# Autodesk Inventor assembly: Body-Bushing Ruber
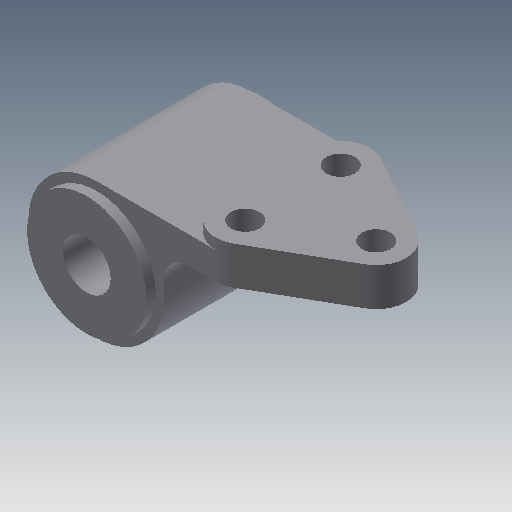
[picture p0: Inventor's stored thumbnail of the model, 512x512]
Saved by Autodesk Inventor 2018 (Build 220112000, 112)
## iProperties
Created: 2011-07
Part Number: Body-Bushing Ruber
Document SubType Name: Assembly
Designer: CadCim
Author: CadCim
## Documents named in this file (3)
- E:\_Deepak\Inventor\Autodesk Inventor_2017_Project\Resources\Inventor_2018_tut\c09_Inv_tut_2018\c09_tut03_inv\Anti Vibration Mount\Body-Bushing Ruber.iam
- E:\_Deepak\Inventor\Autodesk Inventor_2017_Project\Resources\Inventor_2018_tut\c09_Inv_tut_2018\c09_tut03_inv\Anti Vibration Mount\Body.ipt
- E:\_Deepak\Inventor\Autodesk Inventor_2017_Project\Resources\Inventor_2018_tut\c09_Inv_tut_2018\c09_tut03_inv\Anti Vibration Mount\Bushing Rubber.ipt
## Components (3 placed, 2 different names)
1. Body:1 — Insert:1, Insert:2
2. Bushing Rubber:1 — Insert:1
3. Bushing Rubber:2 — Insert:2
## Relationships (2: Insert 2)
- Insert:1: Body:1 ↔ Bushing Rubber:1
- Insert:2: Body:1 ↔ Bushing Rubber:2
